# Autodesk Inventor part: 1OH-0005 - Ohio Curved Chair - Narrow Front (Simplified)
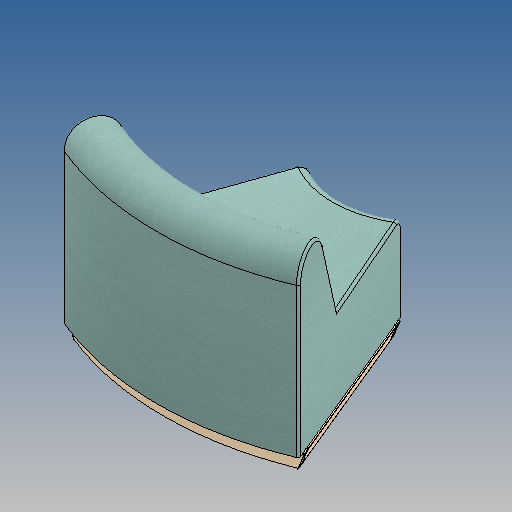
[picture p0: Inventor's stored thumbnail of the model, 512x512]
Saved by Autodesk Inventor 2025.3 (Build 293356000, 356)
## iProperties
Created: 2025-11
Part Number: 1OH-0005 - Ohio Curved Chair - Narrow Front (Simplified)
Material: Generic
Document SubType Name: Modeling
Designer: craig.ferris
Density: 1 g/cm^3
Appearance: CADET-ZEST SEAFOAM (219)
Author: craig.ferris
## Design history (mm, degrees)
derived "1OH-0005 - Ohio Curved Chair - Narrow Front (Rev C).iam"
body "Solid1"
body "Solid2"
body "Solid3"
body "Solid4"
body "Solid5"
body "Solid6"
body "Solid7"
body "Solid8"
body "Solid9"
body "Solid10"
body "Solid11"
